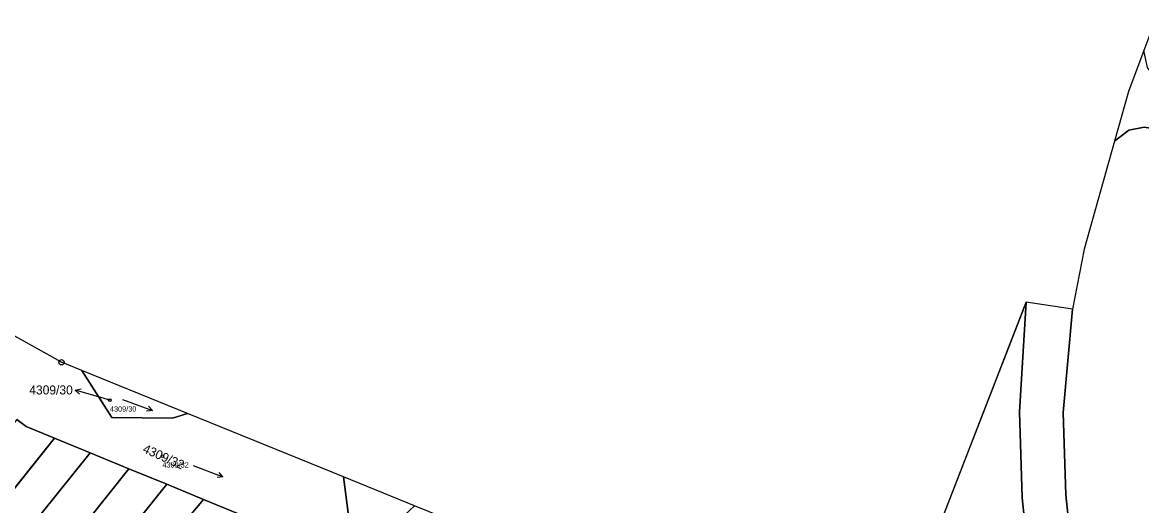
# Model space of a CAD drawing. Extents: x -739214 to -733252, y -1147612 to -1142842.
# Drawn here: x -737498.6 to -737287.3, y -1144291.6 to -1144200.4 of the extents above; entities that cross this region are included whole.
import ezdxf

# ---------------------------------------------------------------- set-up
doc = ezdxf.new("R2010")
doc.units = 0
for name, color, linetype in [('Definiční body', 7, 'Continuous'), ('Hranice parcel', 7, 'Continuous'), ('Parcelní čísla', 7, 'Continuous'), ('Polygon ku', 7, 'Continuous'), ('Polygon parcely', 7, 'Continuous'), ('Pop  PČ popisy', 7, 'Continuous'), ('Značky bodu BP', 7, 'Continuous'), ('Značky kultur', 7, 'Continuous')]:
    doc.layers.add(name, color=color, linetype=linetype)

msp = doc.modelspace()

# ---------------------------------------------------------------- linework, layer by layer
at = {"layer": 'Definiční body'}
for centre in [(-737482.09, -1144271.74), (-737472.19, -1144282.3)]:
    msp.add_circle(centre, 0.25, dxfattribs=at)
at = {"layer": 'Hranice parcel'}
for p, q in [((-737338.64, -1144329.35), (-737309.06, -1144253.23)), ((-737300.34, -1144254.54), (-737309.06, -1144253.23)), ((-737491.23, -1144264.59), (-737500.02, -1144259.67)), ((-737487.38, -1144266.16), (-737491.23, -1144264.59)), ((-737467.45, -1144274.25), (-737487.38, -1144266.16)), ((-737438.01, -1144286.21), (-737467.45, -1144274.25)), ((-737515.43, -1144307.53), (-737492.56, -1144278.89)), ((-737485.8, -1144281.68), (-737492.56, -1144278.89)), ((-737478.52, -1144284.68), (-737485.8, -1144281.68)), ((-737502.07, -1144314.24), (-737478.52, -1144284.68)), ((-737471.37, -1144287.62), (-737478.52, -1144284.68)), ((-737438.01, -1144286.21), (-737435.9, -1144302.23)), ((-737424.58, -1144291.67), (-737438.01, -1144286.21)), ((-737496.81, -1144319.43), (-737471.37, -1144287.62)), ((-737464.42, -1144290.48), (-737471.37, -1144287.62)), ((-737492.92, -1144324.38), (-737464.42, -1144290.48)), ((-737456.75, -1144293.64), (-737464.42, -1144290.48))]:
    msp.add_line(p, q, dxfattribs=at)
for points in [[(-737286.87, -1144205.75), (-737289.75, -1144213.45), (-737292.4, -1144222.86)], [(-737258.21, -1144228.62), (-737283.61, -1144220.69), (-737286.81, -1144220.22), (-737289.71, -1144220.77), (-737292.4, -1144222.86)], [(-737292.4, -1144222.86), (-737298.13, -1144243.21), (-737300.34, -1144254.54)], [(-737309.06, -1144253.23), (-737310.36, -1144273.94), (-737309.81, -1144290.18), (-737307.22, -1144315.31), (-737306.82, -1144317.55)], [(-737289.67, -1144393.05), (-737289.62, -1144376.07), (-737291.38, -1144358.48), (-737294.61, -1144338.39), (-737299.04, -1144314.14), (-737301.57, -1144289.62), (-737302.08, -1144274.04), (-737300.34, -1144254.54)], [(-737487.38, -1144266.16), (-737481.75, -1144275), (-737470.28, -1144275.15), (-737467.45, -1144274.25)], [(-737492.56, -1144278.89), (-737497.9, -1144276.69), (-737499.7, -1144275.41)], [(-737509.32, -1144310.65), (-737501.23, -1144300.88), (-737485.8, -1144281.68)]]:
    msp.add_lwpolyline(points, dxfattribs=at)
at = {"layer": 'Polygon ku'}
for points in [[(-737110.11, -1143982.53), (-737121.1, -1143996.03), (-737150.18, -1144031.76), (-737176.99, -1144064.7), (-737188.45, -1144078.78), (-737213.57, -1144106.87), (-737233.53, -1144129.19), (-737262.38, -1144163.65), (-737282.7, -1144194.6), (-737286.87, -1144205.75), (-737289.75, -1144213.45), (-737292.4, -1144222.86), (-737298.13, -1144243.21), (-737300.34, -1144254.54), (-737309.06, -1144253.23)], [(-737309.06, -1144253.23), (-737338.64, -1144329.35), (-737348.64, -1144340.82), (-737352.83, -1144345.62), (-737361.52, -1144332.23), (-737373.47, -1144318.58), (-737375.25, -1144317.2), (-737383.89, -1144310.52), (-737397.98, -1144302.48), (-737398.82, -1144302.14), (-737408.73, -1144298.11), (-737424.58, -1144291.67), (-737438.01, -1144286.21), (-737467.45, -1144274.25), (-737487.38, -1144266.16), (-737491.23, -1144264.59), (-737500.02, -1144259.67)]]:
    msp.add_lwpolyline(points, dxfattribs=at)
at = {"layer": 'Polygon parcely'}
for points in [[(-737111.93, -1144272.53), (-737127.47, -1144266.96), (-737162.79, -1144250.91), (-737201.22, -1144238.01), (-737281.48, -1144212.97), (-737284.47, -1144211.29), (-737286.16, -1144208.95), (-737286.87, -1144205.75), (-737289.75, -1144213.45), (-737292.4, -1144222.86), (-737289.71, -1144220.77), (-737286.81, -1144220.22), (-737283.61, -1144220.69), (-737258.21, -1144228.62), (-737233.63, -1144236.29), (-737203.69, -1144245.63), (-737193.84, -1144248.94), (-737165.91, -1144258.74), (-737133.26, -1144273.13), (-737130.74, -1144274.68), (-737128.56, -1144276.65), (-737126.68, -1144279.31), (-737125.01, -1144283.41), (-737114.91, -1144276.02)], [(-737499.7, -1144275.41), (-737497.9, -1144276.69), (-737492.56, -1144278.89), (-737485.8, -1144281.68), (-737478.52, -1144284.68), (-737471.37, -1144287.62), (-737464.42, -1144290.48), (-737456.75, -1144293.64), (-737450.05, -1144296.4), (-737442.78, -1144299.39), (-737437.08, -1144301.74), (-737435.9, -1144302.23), (-737438.01, -1144286.21), (-737467.45, -1144274.25), (-737470.28, -1144275.15), (-737481.75, -1144275), (-737487.38, -1144266.16), (-737491.23, -1144264.59), (-737500.02, -1144259.67)]]:
    msp.add_lwpolyline(points, dxfattribs=at)
for points in [[(-737300.34, -1144254.54), (-737302.08, -1144274.04), (-737301.57, -1144289.62), (-737299.04, -1144314.14), (-737294.61, -1144338.39), (-737291.38, -1144358.48), (-737289.62, -1144376.07), (-737289.67, -1144393.05), (-737273.45, -1144379), (-737258.76, -1144367.26), (-737258.21, -1144228.62), (-737283.61, -1144220.69), (-737286.81, -1144220.22), (-737289.71, -1144220.77), (-737292.4, -1144222.86), (-737298.13, -1144243.21)], [(-737338.64, -1144329.35), (-737306.82, -1144317.55), (-737307.22, -1144315.31), (-737309.81, -1144290.18), (-737310.36, -1144273.94), (-737309.06, -1144253.23)], [(-737300.34, -1144254.54), (-737309.06, -1144253.23), (-737310.36, -1144273.94), (-737309.81, -1144290.18), (-737307.22, -1144315.31), (-737306.82, -1144317.55), (-737302.75, -1144339.79), (-737301.31, -1144348.74), (-737299.57, -1144359.55), (-737298.24, -1144372.87), (-737297.88, -1144376.47), (-737297.93, -1144393.12), (-737297.22, -1144393.11), (-737289.67, -1144393.05), (-737289.62, -1144376.07), (-737291.38, -1144358.48), (-737294.61, -1144338.39), (-737299.04, -1144314.14), (-737301.57, -1144289.62), (-737302.08, -1144274.04)], [(-737487.38, -1144266.16), (-737481.75, -1144275), (-737470.28, -1144275.15), (-737467.45, -1144274.25)], [(-737492.56, -1144278.89), (-737497.9, -1144276.69), (-737499.7, -1144275.41), (-737522.37, -1144303.94), (-737515.43, -1144307.53)], [(-737485.8, -1144281.68), (-737492.56, -1144278.89), (-737515.43, -1144307.53), (-737509.32, -1144310.65), (-737501.23, -1144300.88)], [(-737478.52, -1144284.68), (-737485.8, -1144281.68), (-737501.23, -1144300.88), (-737509.32, -1144310.65), (-737502.07, -1144314.24)], [(-737471.37, -1144287.62), (-737478.52, -1144284.68), (-737502.07, -1144314.24), (-737500.24, -1144315.38), (-737496.81, -1144319.43)], [(-737438.01, -1144286.21), (-737435.9, -1144302.23), (-737424.58, -1144291.67)], [(-737464.42, -1144290.48), (-737471.37, -1144287.62), (-737496.81, -1144319.43), (-737492.92, -1144324.38)], [(-737477.89, -1144318.64), (-737456.75, -1144293.64), (-737464.42, -1144290.48), (-737492.92, -1144324.38), (-737486.67, -1144329.49)]]:
    msp.add_lwpolyline(points, close=True, dxfattribs=at)
at = {"layer": 'Pop  PČ popisy'}
for p, q in [((-737488.65, -1144269.83), (-737487.54, -1144269.63)), ((-737485.76, -1144270.66), (-737488.65, -1144269.83)), ((-737488.65, -1144269.83), (-737487.82, -1144270.59)), ((-737482.09, -1144271.74), (-737485.76, -1144270.66))]:
    msp.add_line(p, q, dxfattribs=at)
at = {"layer": 'Značky bodu BP'}
for radius in [0.5, 0.0303]:
    msp.add_circle((-737491.23, -1144264.59), radius, dxfattribs=at)
at = {"layer": 'Značky kultur'}
for p, q in [((-737479.72, -1144271.63), (-737474.08, -1144273.68)), ((-737474.08, -1144273.68), (-737475.17, -1144273.82)), ((-737474.08, -1144273.68), (-737474.82, -1144272.88)), ((-737466.35, -1144284.07), (-737460.75, -1144286.22)), ((-737460.75, -1144286.22), (-737461.84, -1144286.34)), ((-737460.75, -1144286.22), (-737461.48, -1144285.4))]:
    msp.add_line(p, q, dxfattribs=at)

# ---------------------------------------------------------------- texts
at = {"layer": 'Definiční body'}
for s, p in [('4309/30', (-737482.09, -1144273.9)), ('4309/32', (-737472.19, -1144284.46))]:
    msp.add_text(s, height=1, dxfattribs=at).set_placement(p)
at = {"layer": 'Parcelní čísla'}
msp.add_text('4309/30', height=1.7, dxfattribs=at).set_placement((-737497.32, -1144270.66))
msp.add_text('4309/32', height=1.7, rotation=336, dxfattribs=at).set_placement((-737476.04, -1144281.52))

doc.saveas('drawing.dxf')
